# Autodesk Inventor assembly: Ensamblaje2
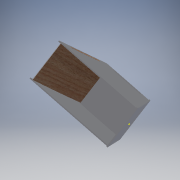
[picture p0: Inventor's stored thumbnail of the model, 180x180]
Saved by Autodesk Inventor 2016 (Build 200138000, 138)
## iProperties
Created: 2016-06
Part Number: Ensamblaje2
Material: Genérico
Document SubType Name: Assembly
Designer: adm
Author: adm
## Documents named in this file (6)
- C:\Users\adm\Desktop\recepcion 2\Ensamblaje2.iam
- C:\Users\adm\Desktop\recepcion 2\parte porterior.ipt
- C:\Users\adm\Desktop\recepcion 2\laterales(2).ipt
- C:\Users\adm\Desktop\recepcion 2\lado inclinado.ipt
- C:\Users\adm\Desktop\recepcion 2\base.ipt
- C:\Users\adm\Desktop\recepcion 2\laterales.ipt
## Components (6 placed, 5 different names)
1. parte porterior:1 — Coincidencia:4, Coincidencia:5, Nivelación:2, Coincidencia:10, Nivelación:3, Coincidencia:11, Coincidencia:12, Nivelación:4, Coincidencia:13, Coincidencia:14, Coincidencia:15, Nivelación:5
2. laterales(2):2 — Coincidencia:4, Coincidencia:5
3. lado inclinado:1 — Coincidencia:20, Nivelación:7
4. base:1 — Nivelación:2, Coincidencia:10, Nivelación:3, Coincidencia:11, Coincidencia:14, Coincidencia:15, Coincidencia:16, Coincidencia:17, Coincidencia:18, Coincidencia:19, Nivelación:6
5. laterales:1 — Coincidencia:12, Nivelación:4, Coincidencia:13, Coincidencia:19, Nivelación:6
6. laterales:2 — Coincidencia:16, Coincidencia:17, Coincidencia:18, Nivelación:5, Coincidencia:20, Nivelación:7
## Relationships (19: Mate 13, Flush 6)
- Coincidencia:4 [Mate]: parte porterior:1 ↔ laterales(2):2
- Coincidencia:5 [Mate]: parte porterior:1 ↔ laterales(2):2
- Nivelación:2 [Flush]: parte porterior:1 ↔ base:1
- Coincidencia:10 [Mate]: parte porterior:1 ↔ base:1
- Nivelación:3 [Flush]: parte porterior:1 ↔ base:1
- Coincidencia:11 [Mate]: parte porterior:1 ↔ base:1
- Coincidencia:12 [Mate]: parte porterior:1 ↔ laterales:1
- Nivelación:4 [Flush]: parte porterior:1 ↔ laterales:1
- Coincidencia:13 [Mate]: parte porterior:1 ↔ laterales:1
- Coincidencia:14 [Mate]: parte porterior:1 ↔ base:1
- Coincidencia:15 [Mate]: parte porterior:1 ↔ base:1
- Coincidencia:16 [Mate]: base:1 ↔ laterales:2
- Coincidencia:17 [Mate]: base:1 ↔ laterales:2
- Coincidencia:18 [Mate]: base:1 ↔ laterales:2
- Coincidencia:19 [Mate]: base:1 ↔ laterales:1
- Nivelación:5 [Flush]: parte porterior:1 ↔ laterales:2
- Nivelación:6 [Flush]: base:1 ↔ laterales:1
- Coincidencia:20 [Mate]: lado inclinado:1 ↔ laterales:2
- Nivelación:7 [Flush]: lado inclinado:1 ↔ laterales:2
